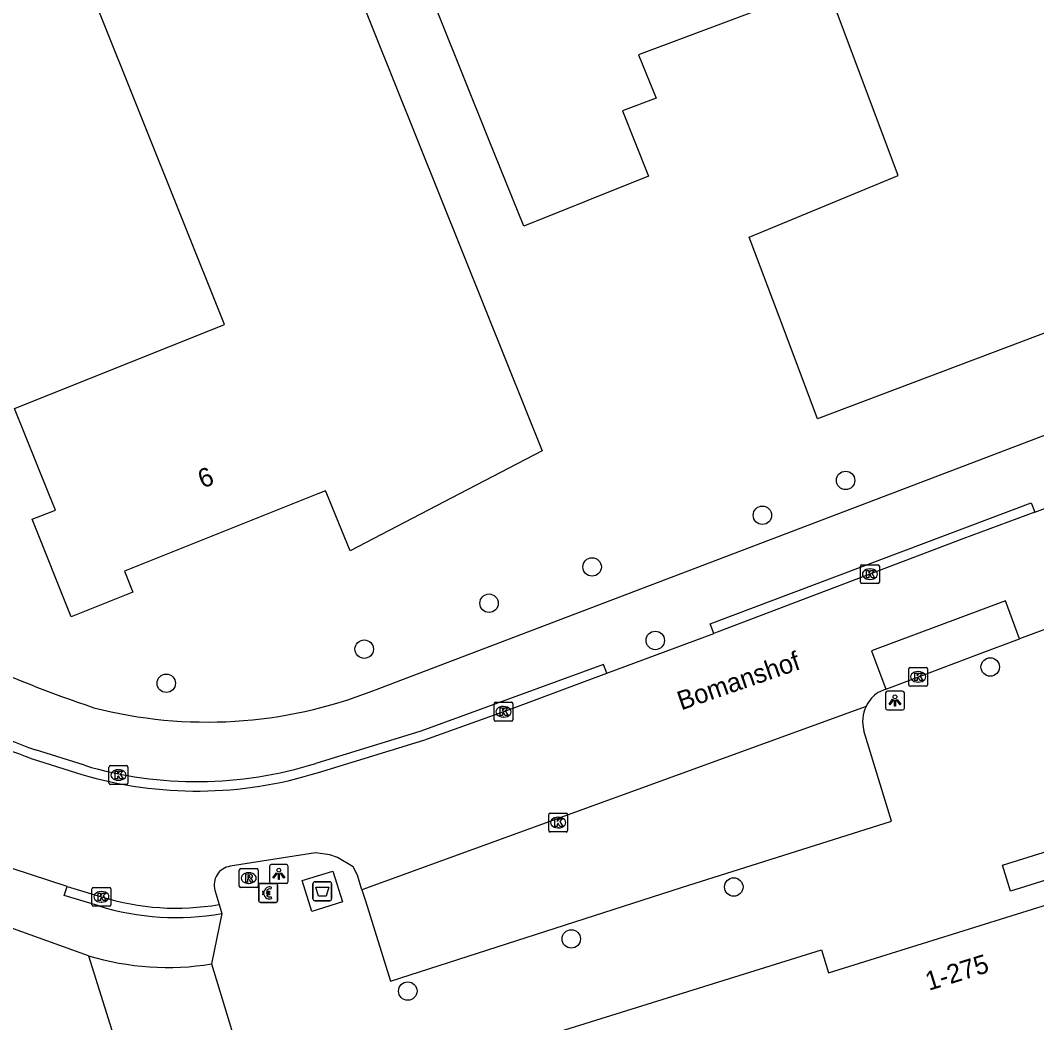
# Model space of a CAD drawing. Extents: x 161354 to 161876, y 382161 to 382804.
# Drawn here: x 161724.3 to 161778.2, y 382471.9 to 382525.1 of the extents above; entities that cross this region are included whole.
import ezdxf

# ---------------------------------------------------------------- set-up
doc = ezdxf.new("R2010")
doc.units = 0
for name, color, linetype in [('IMGEO_Afval_apart_plaats', 7, 'Continuous'), ('IMGEO_Betaalautomaat', 7, 'Continuous'), ('IMGEO_Boom', 7, 'Continuous'), ('IMGEO_Kolk', 7, 'Continuous'), ('IMGEO_Lichtpunt', 7, 'Continuous'), ('IMGEO_Openbare_ruimte_label', 7, 'Continuous'), ('IMGEO_Pand', 7, 'Continuous'), ('IMGEO_Pand_nummerreeks', 7, 'Continuous'), ('IMGEO_Rijbaan_lokaal_open', 7, 'Continuous'), ('IMGEO_Rioolput', 7, 'Continuous'), ('IMGEO_Voetpad_gesloten', 7, 'Continuous'), ('IMGEO_Voetpad_open', 7, 'Continuous')]:
    doc.layers.add(name, color=color, linetype=linetype)

msp = doc.modelspace()

# ---------------------------------------------------------------- linework, layer by layer
at = {"layer": 'IMGEO_Afval_apart_plaats'}
for p, q in [((161739.946, 382479.421), (161740.736, 382479.421)), ((161740.736, 382479.421), (161739.946, 382479.421)), ((161739.846, 382478.521), (161739.846, 382479.321)), ((161739.846, 382479.321), (161739.846, 382478.521)), ((161740.836, 382479.321), (161740.836, 382478.521)), ((161740.836, 382478.521), (161740.836, 382479.321)), ((161740.736, 382478.421), (161739.946, 382478.421)), ((161739.946, 382478.421), (161740.736, 382478.421))]:
    msp.add_line(p, q, dxfattribs=at)
msp.add_lwpolyline([(161739.989, 382479.135), (161740.693, 382479.135), (161740.544, 382478.665), (161740.138, 382478.665), (161739.989, 382479.135)], dxfattribs=at)
for centre, start, end in [((161739.946, 382479.321), 90, 180), ((161739.946, 382479.321), 90, 180), ((161740.736, 382479.321), 0, 90), ((161740.736, 382479.321), 360, 90), ((161739.946, 382478.521), 180, 270), ((161739.946, 382478.521), 180, 270), ((161740.736, 382478.521), 270, 0), ((161740.736, 382478.521), 270, 0)]:
    msp.add_arc(centre, 0.1, start, end, dxfattribs=at)
at = {"layer": 'IMGEO_Betaalautomaat'}
for p, q in [((161736.971, 382478.407), (161736.971, 382479.248)), ((161736.971, 382479.248), (161736.971, 382478.407)), ((161737.046, 382479.331), (161737.887, 382479.331)), ((161737.887, 382479.331), (161737.046, 382479.331)), ((161737.254, 382478.795), (161737.254, 382478.863)), ((161737.375, 382478.863), (161737.375, 382478.795)), ((161737.633, 382479.136), (161737.616, 382479.036)), ((161737.97, 382479.257), (161737.97, 382478.416)), ((161737.97, 382478.416), (161737.97, 382479.257)), ((161737.896, 382478.332), (161737.055, 382478.332)), ((161737.055, 382478.332), (161737.896, 382478.332)), ((161737.62, 382478.63), (161737.642, 382478.543))]:
    msp.add_line(p, q, dxfattribs=at)
for points in [[(161737.254, 382478.863), (161737.185, 382478.863), (161737.185, 382478.932), (161737.264, 382478.932)], [(161737.386, 382478.932), (161737.533, 382478.932), (161737.533, 382478.863), (161737.375, 382478.863)], [(161737.259, 382478.726), (161737.185, 382478.726), (161737.185, 382478.795), (161737.254, 382478.795)], [(161737.375, 382478.795), (161737.533, 382478.795), (161737.533, 382478.726), (161737.389, 382478.726)]]:
    msp.add_lwpolyline(points, dxfattribs=at)
for centre, radius, start, end in [((161737.049, 382479.254), 0.0779, 92.4484, 184.2845), ((161737.049, 382479.254), 0.0779, 92.4484, 184.2845), ((161737.547, 382478.856), 0.293, 73.014, 165.0139), ((161737.553, 382478.869), 0.179, 69.3236, 159.5683), ((161737.893, 382479.254), 0.0779, 2.4484, 94.2845), ((161737.893, 382479.254), 0.0779, 2.4484, 94.2845), ((161737.049, 382478.41), 0.0779, 182.4484, 274.2845), ((161737.049, 382478.41), 0.0779, 182.4484, 274.2845), ((161737.52, 382478.781), 0.267, 191.8096, 297.0389), ((161737.553, 382478.796), 0.179, 202.7625, 291.8693), ((161737.893, 382478.41), 0.0779, 272.4484, 4.2845), ((161737.893, 382478.41), 0.0779, 272.4484, 4.2845)]:
    msp.add_arc(centre, radius, start, end, dxfattribs=at)
at = {"layer": 'IMGEO_Boom'}
for centre in [(161768.094, 382500.712), (161763.684, 382498.865), (161754.651, 382496.123), (161749.185, 382494.199), (161757.998, 382492.223), (161742.562, 382491.762), (161775.765, 382490.817), (161732.061, 382489.952), (161762.165, 382479.147), (161753.544, 382476.394), (161744.875, 382473.625)]:
    msp.add_circle(centre, 0.489, dxfattribs=at)
at = {"layer": 'IMGEO_Kolk'}
for p, q in [((161768.886, 382495.312), (161768.886, 382496.164)), ((161768.961, 382496.238), (161769.813, 382496.238)), ((161769.887, 382496.164), (161769.887, 382495.312)), ((161769.374, 382496.018), (161769.399, 382496.018)), ((161769.813, 382495.238), (161768.961, 382495.238)), ((161769.397, 382495.458), (161769.372, 382495.458)), ((161771.521, 382490.791), (161772.373, 382490.791)), ((161771.446, 382489.865), (161771.446, 382490.717)), ((161771.934, 382490.571), (161771.959, 382490.571)), ((161772.447, 382490.717), (161772.447, 382489.865)), ((161772.373, 382489.791), (161771.521, 382489.791)), ((161771.957, 382490.011), (161771.932, 382490.011)), ((161749.449, 382488.016), (161749.449, 382488.868)), ((161749.524, 382488.942), (161750.376, 382488.942)), ((161749.937, 382488.722), (161749.962, 382488.722)), ((161750.45, 382488.868), (161750.45, 382488.016)), ((161749.96, 382488.162), (161749.935, 382488.162)), ((161750.376, 382487.942), (161749.524, 382487.942)), ((161729.026, 382484.659), (161729.026, 382485.511)), ((161729.101, 382485.585), (161729.953, 382485.585)), ((161729.514, 382485.365), (161729.539, 382485.365)), ((161730.027, 382485.511), (161730.027, 382484.659)), ((161729.537, 382484.805), (161729.512, 382484.805)), ((161729.953, 382484.585), (161729.101, 382484.585)), ((161752.348, 382482.138), (161752.348, 382482.99)), ((161752.423, 382483.064), (161753.275, 382483.064)), ((161752.836, 382482.844), (161752.861, 382482.844)), ((161753.349, 382482.99), (161753.349, 382482.138)), ((161752.859, 382482.284), (161752.834, 382482.284)), ((161753.275, 382482.064), (161752.423, 382482.064)), ((161728.124, 382478.197), (161728.124, 382479.049)), ((161728.199, 382479.123), (161729.051, 382479.123)), ((161728.612, 382478.903), (161728.637, 382478.903)), ((161729.125, 382479.049), (161729.125, 382478.197)), ((161728.635, 382478.343), (161728.61, 382478.343)), ((161729.051, 382478.123), (161728.199, 382478.123))]:
    msp.add_line(p, q, dxfattribs=at)
for points in [[(161768.886, 382495.312), (161768.886, 382496.164)], [(161768.961, 382496.238), (161769.813, 382496.238)], [(161769.887, 382496.164), (161769.887, 382495.312)], [(161769.207, 382495.938), (161769.33, 382495.938), (161769.33, 382495.787), (161769.46, 382495.938), (161769.624, 382495.938), (161769.478, 382495.787), (161769.631, 382495.538), (161769.479, 382495.538), (161769.394, 382495.702), (161769.33, 382495.635), (161769.33, 382495.538), (161769.207, 382495.538), (161769.207, 382495.938)], [(161769.813, 382495.238), (161768.961, 382495.238)], [(161771.521, 382490.791), (161772.373, 382490.791)], [(161771.446, 382489.865), (161771.446, 382490.717)], [(161771.767, 382490.491), (161771.89, 382490.491), (161771.89, 382490.34), (161772.02, 382490.491), (161772.184, 382490.491), (161772.038, 382490.34), (161772.191, 382490.091), (161772.039, 382490.091), (161771.954, 382490.255), (161771.89, 382490.188), (161771.89, 382490.091), (161771.767, 382490.091), (161771.767, 382490.491)], [(161772.447, 382490.717), (161772.447, 382489.865)], [(161772.373, 382489.791), (161771.521, 382489.791)], [(161749.449, 382488.016), (161749.449, 382488.868)], [(161749.524, 382488.942), (161750.376, 382488.942)], [(161749.77, 382488.642), (161749.893, 382488.642), (161749.893, 382488.491), (161750.023, 382488.642), (161750.187, 382488.642), (161750.041, 382488.491), (161750.194, 382488.242), (161750.042, 382488.242), (161749.957, 382488.406), (161749.893, 382488.339), (161749.893, 382488.242), (161749.77, 382488.242), (161749.77, 382488.642)], [(161750.45, 382488.868), (161750.45, 382488.016)], [(161750.376, 382487.942), (161749.524, 382487.942)], [(161729.026, 382484.659), (161729.026, 382485.511)], [(161729.101, 382485.585), (161729.953, 382485.585)], [(161730.027, 382485.511), (161730.027, 382484.659)], [(161729.347, 382485.285), (161729.47, 382485.285), (161729.47, 382485.134), (161729.6, 382485.285), (161729.764, 382485.285), (161729.618, 382485.134), (161729.771, 382484.885), (161729.619, 382484.885), (161729.534, 382485.049), (161729.47, 382484.982), (161729.47, 382484.885), (161729.347, 382484.885), (161729.347, 382485.285)], [(161729.953, 382484.585), (161729.101, 382484.585)], [(161752.348, 382482.138), (161752.348, 382482.99)], [(161752.423, 382483.064), (161753.275, 382483.064)], [(161752.669, 382482.764), (161752.792, 382482.764), (161752.792, 382482.613), (161752.922, 382482.764), (161753.086, 382482.764), (161752.94, 382482.613), (161753.093, 382482.364), (161752.941, 382482.364), (161752.856, 382482.528), (161752.792, 382482.461), (161752.792, 382482.364), (161752.669, 382482.364), (161752.669, 382482.764)], [(161753.349, 382482.99), (161753.349, 382482.138)], [(161753.275, 382482.064), (161752.423, 382482.064)], [(161728.124, 382478.197), (161728.124, 382479.049)], [(161728.199, 382479.123), (161729.051, 382479.123)], [(161729.125, 382479.049), (161729.125, 382478.197)], [(161728.445, 382478.823), (161728.568, 382478.823), (161728.568, 382478.672), (161728.698, 382478.823), (161728.862, 382478.823), (161728.716, 382478.672), (161728.869, 382478.423), (161728.717, 382478.423), (161728.632, 382478.587), (161728.568, 382478.52), (161728.568, 382478.423), (161728.445, 382478.423), (161728.445, 382478.823)], [(161729.051, 382478.123), (161728.199, 382478.123)]]:
    msp.add_lwpolyline(points, dxfattribs=at)
for centre, start, end in [((161768.963, 382496.162), 91.552, 178.448), ((161768.963, 382496.162), 91.552, 178.448), ((161769.811, 382496.162), 1.552, 88.448), ((161769.811, 382496.162), 1.552, 88.448), ((161768.963, 382495.314), 181.552, 268.448), ((161768.963, 382495.314), 181.552, 268.448), ((161769.811, 382495.314), 271.552, 358.448), ((161769.811, 382495.314), 271.552, 358.448), ((161771.523, 382490.715), 91.552, 178.448), ((161771.523, 382490.715), 91.552, 178.448), ((161772.371, 382490.715), 1.552, 88.448), ((161772.371, 382490.715), 1.552, 88.448), ((161771.523, 382489.867), 181.552, 268.448), ((161771.523, 382489.867), 181.552, 268.448), ((161772.371, 382489.867), 271.552, 358.448), ((161772.371, 382489.867), 271.552, 358.448), ((161749.526, 382488.866), 91.552, 178.448), ((161749.526, 382488.866), 91.552, 178.448), ((161750.374, 382488.866), 1.552, 88.448), ((161750.374, 382488.866), 1.552, 88.448), ((161749.526, 382488.018), 181.552, 268.448), ((161749.526, 382488.018), 181.552, 268.448), ((161750.374, 382488.018), 271.552, 358.448), ((161750.374, 382488.018), 271.552, 358.448), ((161729.103, 382485.509), 91.552, 178.448), ((161729.103, 382485.509), 91.552, 178.448), ((161729.951, 382485.509), 1.552, 88.448), ((161729.951, 382485.509), 1.552, 88.448), ((161729.103, 382484.661), 181.552, 268.448), ((161729.103, 382484.661), 181.552, 268.448), ((161729.951, 382484.661), 271.552, 358.448), ((161729.951, 382484.661), 271.552, 358.448), ((161752.425, 382482.988), 91.552, 178.448), ((161752.425, 382482.988), 91.552, 178.448), ((161753.273, 382482.988), 1.552, 88.448), ((161753.273, 382482.988), 1.552, 88.448), ((161752.425, 382482.14), 181.552, 268.448), ((161752.425, 382482.14), 181.552, 268.448), ((161753.273, 382482.14), 271.552, 358.448), ((161753.273, 382482.14), 271.552, 358.448), ((161728.201, 382479.047), 91.552, 178.448), ((161728.201, 382479.047), 91.552, 178.448), ((161729.049, 382479.047), 1.552, 88.448), ((161729.049, 382479.047), 1.552, 88.448), ((161728.201, 382478.199), 181.552, 268.448), ((161728.201, 382478.199), 181.552, 268.448), ((161729.049, 382478.199), 271.552, 358.448), ((161729.049, 382478.199), 271.552, 358.448)]:
    msp.add_arc(centre, 0.0765, start, end, dxfattribs=at)
for centre, major_axis, ratio, start_param, end_param in [((161769.373, 382495.738), (-0.387, 0.002), 0.722429, 4.712389, 7.853982), ((161769.398, 382495.738), (-0.39, 0.002), 0.717154, 1.570796, 4.712389), ((161771.933, 382490.291), (-0.387, 0.002), 0.722429, 4.712389, 7.853982), ((161771.958, 382490.291), (-0.39, 0.002), 0.717154, 1.570796, 4.712389), ((161749.936, 382488.442), (-0.387, 0.002), 0.722429, 4.712389, 7.853982), ((161749.961, 382488.442), (-0.39, 0.002), 0.717154, 1.570796, 4.712389), ((161729.513, 382485.085), (-0.387, 0.002), 0.722429, 4.712389, 7.853982), ((161729.538, 382485.085), (-0.39, 0.002), 0.717154, 1.570796, 4.712389), ((161752.835, 382482.564), (-0.387, 0.002), 0.722429, 4.712389, 7.853982), ((161752.86, 382482.564), (-0.39, 0.002), 0.717154, 1.570796, 4.712389), ((161728.611, 382478.623), (-0.387, 0.002), 0.722429, 4.712389, 7.853982), ((161728.636, 382478.623), (-0.39, 0.002), 0.717154, 1.570796, 4.712389)]:
    msp.add_ellipse(centre, major_axis=major_axis, ratio=ratio, start_param=start_param, end_param=end_param, dxfattribs=at)
at = {"layer": 'IMGEO_Lichtpunt'}
for p, q in [((161770.215, 382489.437), (161770.215, 382488.63)), ((161770.215, 382489.437), (161770.215, 382488.63)), ((161771.117, 382489.532), (161770.309, 382489.532)), ((161771.117, 382489.532), (161770.309, 382489.532)), ((161771.211, 382488.63), (161771.211, 382489.437)), ((161771.211, 382488.63), (161771.211, 382489.437)), ((161770.309, 382488.536), (161771.117, 382488.536)), ((161770.309, 382488.536), (161771.117, 382488.536)), ((161737.533, 382480.242), (161737.533, 382479.435)), ((161737.533, 382480.242), (161737.533, 382479.435)), ((161738.435, 382480.337), (161737.627, 382480.337)), ((161738.435, 382480.337), (161737.627, 382480.337)), ((161738.529, 382479.435), (161738.529, 382480.242)), ((161738.529, 382479.435), (161738.529, 382480.242)), ((161737.627, 382479.341), (161738.435, 382479.341)), ((161737.627, 382479.341), (161738.435, 382479.341))]:
    msp.add_line(p, q, dxfattribs=at)
for points in [[(161770.589, 382489.101), (161770.628, 382489.073), (161770.44, 382488.811), (161770.402, 382488.838), (161770.589, 382489.101)], [(161770.801, 382489.073), (161770.839, 382489.1), (161771.026, 382488.838), (161770.987, 382488.81), (161770.801, 382489.073)], [(161770.691, 382489.053), (161770.738, 382489.053), (161770.738, 382488.731), (161770.691, 382488.731), (161770.691, 382489.053)], [(161737.907, 382479.906), (161737.946, 382479.878), (161737.758, 382479.616), (161737.72, 382479.643), (161737.907, 382479.906)], [(161738.009, 382479.858), (161738.056, 382479.858), (161738.056, 382479.536), (161738.009, 382479.536), (161738.009, 382479.858)], [(161738.119, 382479.878), (161738.157, 382479.905), (161738.344, 382479.643), (161738.305, 382479.615), (161738.119, 382479.878)]]:
    msp.add_lwpolyline(points, dxfattribs=at)
for centre in [(161770.714, 382489.235), (161738.032, 382480.04)]:
    msp.add_circle(centre, 0.0994, dxfattribs=at)
for centre, start, end in [((161770.309, 382489.437), 90, 180), ((161770.309, 382489.437), 90, 180), ((161771.117, 382489.437), 0, 90), ((161771.117, 382489.437), 0, 90), ((161770.309, 382488.63), 180, 270), ((161770.309, 382488.63), 180, 270), ((161771.117, 382488.63), 270, 0), ((161771.117, 382488.63), 270, 360), ((161737.627, 382480.242), 90, 180), ((161737.627, 382480.242), 90, 180), ((161738.435, 382480.242), 0, 90), ((161738.435, 382480.242), 0, 90), ((161737.627, 382479.435), 180, 270), ((161737.627, 382479.435), 180, 270), ((161738.435, 382479.435), 270, 0), ((161738.435, 382479.435), 270, 360)]:
    msp.add_arc(centre, 0.0946, start, end, dxfattribs=at)
at = {"layer": 'IMGEO_Pand'}
for points in [[(161787.992, 382535.056), (161795.715, 382514.974), (161766.605, 382503.972), (161764.835, 382508.692), (161762.985, 382513.624), (161770.887, 382516.889), (161767.082, 382527.032), (161757.117, 382523.292), (161758.043, 382520.983), (161756.257, 382520.312), (161757.644, 382516.851), (161751.023, 382514.198), (161749.163, 382518.84), (161743.927, 382531.906)], [(161740.655, 382530.595), (161750.132, 382506.951), (161752.001, 382502.287), (161747.608, 382500), (161741.809, 382496.981), (161740.585, 382500), (161740.517, 382500.167), (161740.099, 382500), (161729.849, 382495.902), (161730.293, 382494.79), (161727.018, 382493.481), (161724.95, 382498.651), (161726.18, 382499.143), (161725.837, 382500), (161724.022, 382504.528), (161728.664, 382506.388), (161735.151, 382508.988), (161728.418, 382525.789), (161735.075, 382528.457)], [(161741.239, 382467.848), (161766.816, 382475.812), (161767.193, 382474.599), (161779.657, 382478.48), (161779.28, 382479.692)]]:
    msp.add_lwpolyline(points, dxfattribs=at)
at = {"layer": 'IMGEO_Rijbaan_lokaal_open'}
for points in [[(161778.125, 382499.034), (161780.715, 382500), (161781.354, 382500.235)], [(161778.125, 382499.034), (161774.32, 382497.616), (161761.289, 382492.657), (161761.104, 382492.588)], [(161777.326, 382492.307), (161776.569, 382494.328), (161769.469, 382491.669), (161770.231, 382489.635)], [(161780.263, 382493.401), (161777.326, 382492.307)], [(161755.432, 382490.481), (161761.104, 382492.588)], [(161740.138, 382485.226), (161745.722, 382486.941), (161750.403, 382488.612), (161755.432, 382490.481)], [(161770.231, 382489.635), (161769.822, 382489.469)], [(161769.186, 382488.728), (161742.445, 382479)], [(161724.95, 382485.948), (161727.579, 382485.122)], [(161742.445, 382479), (161742.203, 382479.781), (161741.976, 382480.223), (161741.141, 382480.712), (161740.743, 382480.856), (161739.975, 382480.953), (161735.45, 382480.246)], [(161726.799, 382479.176), (161723.942, 382480.108), (161723.236, 382480.362)], [(161726.799, 382479.176), (161728.624, 382478.622)], [(161734.644, 382478.978), (161734.865, 382478.218)], [(161727.934, 382475.503), (161740.031, 382436.95)], [(161734.468, 382475.066), (161736.911, 382467.053)]]:
    msp.add_lwpolyline(points, dxfattribs=at)
for centre, radius, start, end in [((161770.888, 382487.91), 1.888, 124.3764, 154.3446), ((161746.351, 382544.343), 62.193, 244.15902, 249.87334), ((161733.688, 382505.718), 21.483, 253.4778, 287.4711), ((161735.604, 382479.258), 1, 98.8765, 196.2396), ((161732.591, 382491.503), 13.479, 252.8814, 279.711), ((161732.141, 382489.337), 14.459, 253.0856, 279.2618)]:
    msp.add_arc(centre, radius, start, end, dxfattribs=at)
at = {"layer": 'IMGEO_Rioolput'}
for p, q in [((161735.937, 382479.194), (161735.937, 382480.046)), ((161736.012, 382480.12), (161736.864, 382480.12)), ((161736.938, 382480.046), (161736.938, 382479.194)), ((161736.425, 382479.9), (161736.45, 382479.9)), ((161736.864, 382479.12), (161736.012, 382479.12)), ((161736.448, 382479.34), (161736.423, 382479.34))]:
    msp.add_line(p, q, dxfattribs=at)
for points in [[(161735.937, 382479.194), (161735.937, 382480.046)], [(161736.012, 382480.12), (161736.864, 382480.12)], [(161736.938, 382480.046), (161736.938, 382479.194)], [(161736.526, 382479.818), (161736.274, 382479.82), (161736.274, 382479.42)], [(161736.274, 382479.42), (161736.398, 382479.42), (161736.398, 382479.582), (161736.409, 382479.582)], [(161736.452, 382479.739), (161736.398, 382479.739), (161736.398, 382479.658)], [(161736.398, 382479.658), (161736.45, 382479.658)], [(161736.456, 382479.553), (161736.527, 382479.42), (161736.667, 382479.42), (161736.602, 382479.546)], [(161736.864, 382479.12), (161736.012, 382479.12)]]:
    msp.add_lwpolyline(points, dxfattribs=at)
for centre, radius, start, end in [((161736.014, 382480.044), 0.0765, 91.552, 178.448), ((161736.014, 382480.044), 0.0765, 91.552, 178.448), ((161736.862, 382480.044), 0.0765, 1.552, 88.448), ((161736.862, 382480.044), 0.0765, 1.552, 88.448), ((161736.408, 382479.529), 0.0533, 26.0293, 88.6989), ((161736.434, 382479.847), 0.19, 274.7715, 282.9687), ((161736.458, 382479.643), 0.0964, 77.0061, 93.1865), ((161736.472, 382479.7), 0.0378, 276.6634, 79.6772), ((161736.525, 382479.708), 0.109, 350.3612, 89.416), ((161736.523, 382479.708), 0.112, 277.5842, 350.9817), ((161736.507, 382479.493), 0.108, 29.5134, 73.7905), ((161736.014, 382479.196), 0.0765, 181.552, 268.448), ((161736.014, 382479.196), 0.0765, 181.552, 268.448), ((161736.862, 382479.196), 0.0765, 271.552, 358.448), ((161736.862, 382479.196), 0.0765, 271.552, 358.448)]:
    msp.add_arc(centre, radius, start, end, dxfattribs=at)
for centre, major_axis, ratio, start_param, end_param in [((161736.424, 382479.62), (-0.387, 0.002), 0.722429, 4.712389, 7.853982), ((161736.449, 382479.62), (-0.39, 0.002), 0.717154, 1.570796, 4.712389)]:
    msp.add_ellipse(centre, major_axis=major_axis, ratio=ratio, start_param=start_param, end_param=end_param, dxfattribs=at)
at = {"layer": 'IMGEO_Voetpad_gesloten'}
msp.add_lwpolyline([(161741.404, 382478.355), (161739.781, 382477.854), (161739.277, 382479.486), (161740.9, 382479.987), (161741.404, 382478.355)], dxfattribs=at)
at = {"layer": 'IMGEO_Voetpad_open'}
for points in [[(161743.028, 382489.559), (161770.47, 382500), (161789.885, 382507.387), (161797.029, 382509.951), (161801.422, 382511.527)], [(161761.104, 382492.588), (161760.912, 382493.098), (161777.944, 382499.515), (161778.125, 382499.034)], [(161770.231, 382489.635), (161770.568, 382489.772), (161775.137, 382491.492), (161777.326, 382492.307)], [(161755.432, 382490.481), (161755.258, 382490.949), (161745.568, 382487.417), (161739.988, 382485.703)], [(161742.445, 382479), (161742.63, 382478.406), (161743.952, 382474.156), (161759.394, 382479.116), (161770.53, 382482.645), (161769.059, 382487.436)], [(161727.721, 382485.601), (161725.122, 382486.417)], [(161779.28, 382479.692), (161776.845, 382478.934), (161776.421, 382480.3), (161778.854, 382481.057)], [(161728.479, 382478.143), (161726.65, 382478.698), (161726.799, 382479.176)], [(161734.865, 382478.218), (161735.005, 382477.734)], [(161727.934, 382475.503), (161722.614, 382477.411)], [(161735.005, 382477.734), (161734.468, 382475.066)]]:
    msp.add_lwpolyline(points, dxfattribs=at)
for centre, radius, start, end in [((161753.222, 382562.309), 77.78, 245.91775, 251.24734), ((161734.231, 382511.977), 24.082, 255.5376, 291.4248), ((161746.285, 382544.176), 61.513, 244.14624, 249.87736), ((161770.898, 382487.907), 1.898, 154.3924, 194.3797), ((161733.688, 382505.731), 20.996, 253.4903, 287.4625), ((161732.589, 382491.448), 13.925, 252.835, 279.9927)]:
    msp.add_arc(centre, radius, start, end, dxfattribs=at)

# ---------------------------------------------------------------- texts
at = {"layer": 'IMGEO_Openbare_ruimte_label'}
msp.add_text('Bomanshof', height=1, rotation=19.0872, dxfattribs=at).set_placement((161759.376, 382488.511))
at = {"layer": 'IMGEO_Pand_nummerreeks'}
for s, rotation, p in [('6', 21.7912, (161733.991, 382500.272)), ('1-275', 17.2954, (161772.509, 382473.636))]:
    msp.add_text(s, height=1, rotation=rotation, dxfattribs=at).set_placement(p)

doc.saveas('drawing.dxf')
